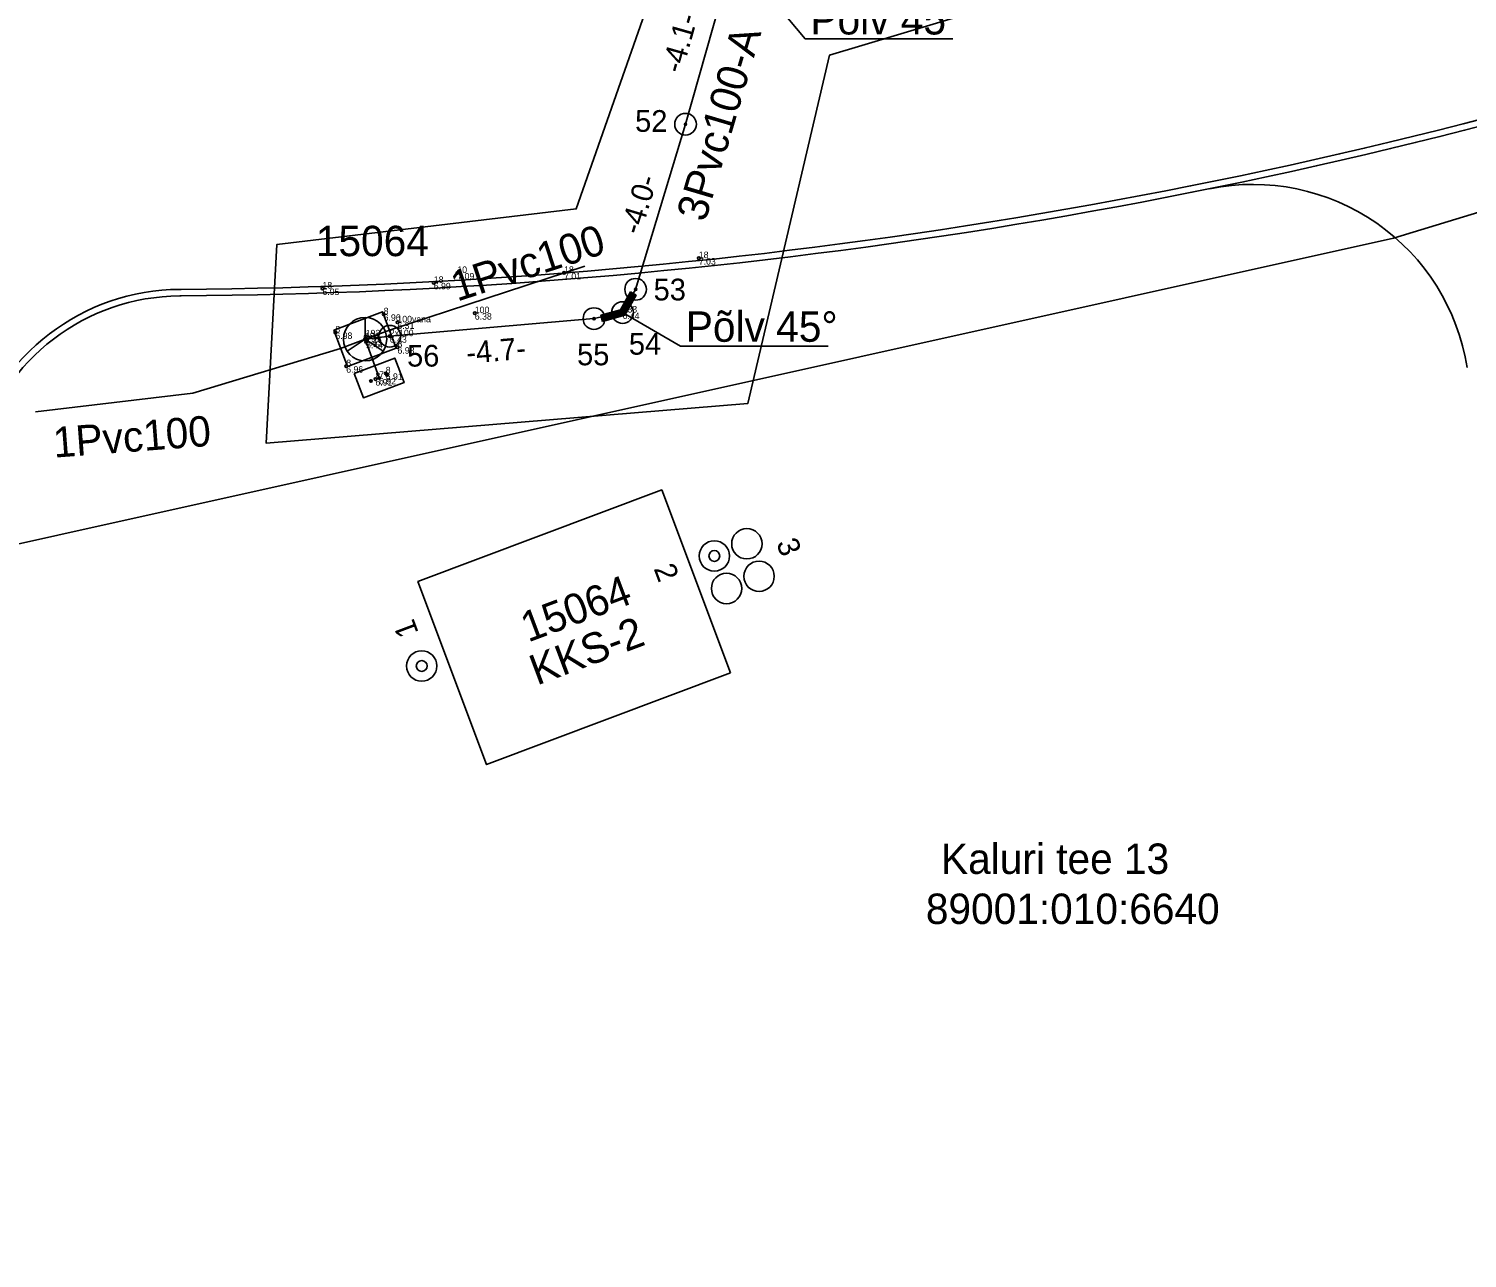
# Model space of a CAD drawing. Extents: x 546339 to 546593, y 6597108 to 6597251.
# Drawn here: x 546356.18 to 546389.31, y 6597127.93 to 6597156.24 of the extents above; entities that cross this region are included whole.
import ezdxf

# ---------------------------------------------------------------- set-up
doc = ezdxf.new("R2010")
doc.units = 0
for name, color, linetype in [('ABIJOONIS', 7, 'Continuous'), ('JOONSIDE', 7, 'Continuous'), ('KAEVUNR_SIKAEV', 7, 'Continuous'), ('KOORDPUNKT', 7, 'Continuous'), ('MOOTKORG-EH2000', 7, 'Continuous'), ('MOOTMPUNKT', 7, 'Continuous'), ('MOOTNR', 7, 'Continuous'), ('MOOTPIIR', 7, 'Continuous'), ('PIIR', 7, 'Continuous'), ('SIKAEV', 7, 'Continuous'), ('SIRAJATIS', 7, 'Continuous'), ('SITRASS', 7, 'Continuous'), ('TEE', 7, 'Continuous')]:
    doc.layers.add(name, color=color, linetype=linetype)

msp = doc.modelspace()

# ---------------------------------------------------------------- linework, layer by layer
at = {"layer": 'ABIJOONIS'}
msp.add_lwpolyline([(546372.341, 6597141.406), (546366.724, 6597139.295), (546365.141, 6597143.507), (546370.757, 6597145.618)], close=True, dxfattribs=at)
for centre, radius in [((546372.719, 6597144.379), 0.35), ((546371.97, 6597144.098), 0.35), ((546371.97, 6597144.098), 0.124), ((546373, 6597143.63), 0.35), ((546372.251, 6597143.349), 0.35), ((546365.23, 6597141.564), 0.35), ((546365.23, 6597141.564), 0.124)]:
    msp.add_circle(centre, radius, dxfattribs=at)
at = {"layer": 'KOORDPUNKT'}
for centre, radius in [((546371.306, 6597154.04), 0.25), ((546371.306, 6597154.04), 0.025), ((546371.306, 6597154.04), 0.0221), ((546371.306, 6597154.04), 0.0191), ((546371.306, 6597154.04), 0.0161), ((546371.306, 6597154.04), 0.0132), ((546371.306, 6597154.04), 0.0102), ((546371.306, 6597154.04), 0.00726), ((546371.306, 6597154.04), 0.0043), ((546370.157, 6597150.238), 0.25), ((546370.157, 6597150.238), 0.025), ((546370.157, 6597150.238), 0.0221), ((546370.157, 6597150.238), 0.0191), ((546370.157, 6597150.238), 0.0161), ((546370.157, 6597150.238), 0.0132), ((546369.857, 6597149.704), 0.25), ((546370.157, 6597150.238), 0.0102), ((546370.157, 6597150.238), 0.00726), ((546370.157, 6597150.238), 0.0043), ((546369.198, 6597149.563), 0.25), ((546369.857, 6597149.704), 0.025), ((546369.857, 6597149.704), 0.0221), ((546369.857, 6597149.704), 0.0191), ((546369.857, 6597149.704), 0.0161), ((546369.857, 6597149.704), 0.0132), ((546369.857, 6597149.704), 0.0102), ((546369.857, 6597149.704), 0.00726), ((546369.857, 6597149.704), 0.0043), ((546364.495, 6597149.159), 0.25), ((546369.198, 6597149.563), 0.025), ((546369.198, 6597149.563), 0.0221), ((546369.198, 6597149.563), 0.0191), ((546369.198, 6597149.563), 0.0161), ((546369.198, 6597149.563), 0.0132), ((546369.198, 6597149.563), 0.0102), ((546369.198, 6597149.563), 0.00726), ((546369.198, 6597149.563), 0.0043), ((546364.495, 6597149.159), 0.025), ((546364.495, 6597149.159), 0.0221), ((546364.495, 6597149.159), 0.0191), ((546364.495, 6597149.159), 0.0161), ((546364.495, 6597149.159), 0.0132), ((546364.495, 6597149.159), 0.0102), ((546364.495, 6597149.159), 0.00726), ((546364.495, 6597149.159), 0.0043)]:
    msp.add_circle(centre, radius, dxfattribs=at)
at = {"layer": 'MOOTMPUNKT'}
for centre in [(546371.612, 6597150.957), (546366.051, 6597150.615), (546368.509, 6597150.618), (546362.944, 6597150.256), (546365.508, 6597150.387), (546364.354, 6597149.663), (546366.453, 6597149.69), (546369.857, 6597149.704), (546363.242, 6597149.245), (546364.671, 6597149.478), (546363.925, 6597149.09), (546363.941, 6597149.155), (546363.948, 6597149.028), (546364.495, 6597149.159), (546364.672, 6597148.906), (546363.492, 6597148.469), (546364.401, 6597148.303), (546364.164, 6597148.172), (546364.248, 6597148.197)]:
    msp.add_circle(centre, 0.03, dxfattribs=at)
at = {"layer": 'MOOTPIIR'}
msp.add_lwpolyline([(546443.888, 6597176.348), (546374.62, 6597155.63), (546372.739, 6597147.606), (546361.644, 6597146.697), (546361.895, 6597151.274), (546368.79, 6597152.088), (546371.486, 6597159.799), (546428.467, 6597177.226), (546428.906, 6597181.927), (546431.038, 6597182.742), (546435.363, 6597179.169)], dxfattribs=at)
at = {"layer": 'PIIR'}
for points in [[(546339.379, 6597150.424), (546339.82, 6597150.4), (546343.3, 6597148.09), (546350.66, 6597143.2), (546387.61, 6597151.42), (546402.5, 6597155.95), (546434.27, 6597166.43), (546452.55, 6597172.32), (546467.66, 6597177.18), (546479.16, 6597180.72), (546505.65, 6597188.82)], [(546405.647, 6597133.544), (546402.5, 6597155.95), (546387.61, 6597151.42), (546350.66, 6597143.2), (546352.148, 6597127.926)]]:
    msp.add_lwpolyline(points, dxfattribs=at)
at = {"layer": 'SIKAEV'}
for p, q in [((546363.925, 6597149.59), (546363.925, 6597149.09)), ((546363.925, 6597149.09), (546363.51, 6597148.815)), ((546363.925, 6597149.09), (546364.34, 6597148.815))]:
    msp.add_line(p, q, dxfattribs=at)
msp.add_lwpolyline([(546363.205, 6597149.3), (546364.328, 6597149.722), (546364.645, 6597148.88), (546363.522, 6597148.458)], close=True, dxfattribs=at)
msp.add_circle((546363.925, 6597149.09), 0.5, dxfattribs=at)
at = {"layer": 'SIRAJATIS'}
msp.add_lwpolyline([(546363.674, 6597148.302), (546364.61, 6597148.654), (546364.822, 6597148.092), (546363.886, 6597147.74)], close=True, dxfattribs=at)
for centre, radius in [((546364.435, 6597148.267), 0.0304), ((546364.435, 6597148.267), 0.029), ((546364.435, 6597148.267), 0.0277), ((546364.435, 6597148.267), 0.0263), ((546364.435, 6597148.267), 0.0249), ((546364.435, 6597148.267), 0.0236), ((546364.435, 6597148.267), 0.0222), ((546364.435, 6597148.267), 0.0209), ((546364.435, 6597148.267), 0.0195), ((546364.435, 6597148.267), 0.0181), ((546364.435, 6597148.267), 0.0168), ((546364.435, 6597148.267), 0.0154), ((546364.435, 6597148.267), 0.014), ((546364.435, 6597148.267), 0.0127), ((546364.435, 6597148.267), 0.0113), ((546364.435, 6597148.267), 0.00996), ((546364.435, 6597148.267), 0.0086), ((546364.435, 6597148.267), 0.00724), ((546364.435, 6597148.267), 0.00587), ((546364.435, 6597148.267), 0.00451), ((546364.435, 6597148.267), 0.00315), ((546364.435, 6597148.267), 0.00179), ((546364.435, 6597148.267), 0.000426), ((546364.061, 6597148.127), 0.0304), ((546364.061, 6597148.127), 0.029), ((546364.061, 6597148.127), 0.0277), ((546364.061, 6597148.127), 0.0263), ((546364.061, 6597148.127), 0.0249), ((546364.061, 6597148.127), 0.0236), ((546364.061, 6597148.127), 0.0222), ((546364.061, 6597148.127), 0.0209), ((546364.061, 6597148.127), 0.0195), ((546364.061, 6597148.127), 0.0181), ((546364.061, 6597148.127), 0.0168), ((546364.061, 6597148.127), 0.0154), ((546364.061, 6597148.127), 0.014), ((546364.061, 6597148.127), 0.0127), ((546364.061, 6597148.127), 0.0113), ((546364.061, 6597148.127), 0.00996), ((546364.061, 6597148.127), 0.0086), ((546364.061, 6597148.127), 0.00724), ((546364.061, 6597148.127), 0.00587), ((546364.061, 6597148.127), 0.00451), ((546364.061, 6597148.127), 0.00315), ((546364.061, 6597148.127), 0.00179), ((546364.061, 6597148.127), 0.000426)]:
    msp.add_circle(centre, radius, dxfattribs=at)
at = {"layer": 'SITRASS'}
for p, q in [((546370.037, 6597150.177), (546369.807, 6597149.768)), ((546370.102, 6597150.14), (546369.857, 6597149.704)), ((546370.167, 6597150.103), (546369.908, 6597149.64)), ((546369.909, 6597149.949), (546369.957, 6597149.728)), ((546369.927, 6597149.981), (546369.975, 6597149.761)), ((546369.945, 6597150.014), (546369.994, 6597149.793)), ((546369.964, 6597150.047), (546370.012, 6597149.826)), ((546369.982, 6597150.08), (546370.03, 6597149.859)), ((546370.001, 6597150.113), (546370.049, 6597149.892)), ((546370.019, 6597150.146), (546370.067, 6597149.925)), ((546370.037, 6597150.177), (546370.167, 6597150.103)), ((546370.038, 6597150.176), (546370.086, 6597149.958)), ((546370.067, 6597150.16), (546370.104, 6597149.991)), ((546370.096, 6597150.143), (546370.123, 6597150.023)), ((546370.126, 6597150.127), (546370.141, 6597150.056)), ((546370.155, 6597150.11), (546370.159, 6597150.089)), ((546369.356, 6597149.641), (546369.807, 6597149.768)), ((546369.356, 6597149.641), (546369.396, 6597149.496)), ((546369.361, 6597149.642), (546369.382, 6597149.548)), ((546369.376, 6597149.569), (546369.857, 6597149.704)), ((546369.385, 6597149.649), (546369.417, 6597149.502)), ((546369.396, 6597149.496), (546369.908, 6597149.64)), ((546369.409, 6597149.656), (546369.442, 6597149.509)), ((546369.434, 6597149.663), (546369.466, 6597149.516)), ((546369.458, 6597149.67), (546369.49, 6597149.523)), ((546369.482, 6597149.676), (546369.514, 6597149.529)), ((546369.506, 6597149.683), (546369.538, 6597149.536)), ((546369.53, 6597149.69), (546369.562, 6597149.543)), ((546369.554, 6597149.697), (546369.586, 6597149.55)), ((546369.578, 6597149.703), (546369.61, 6597149.557)), ((546369.602, 6597149.71), (546369.634, 6597149.563)), ((546369.626, 6597149.717), (546369.658, 6597149.57)), ((546369.651, 6597149.724), (546369.683, 6597149.577)), ((546369.675, 6597149.731), (546369.707, 6597149.584)), ((546369.699, 6597149.737), (546369.731, 6597149.59)), ((546369.723, 6597149.744), (546369.755, 6597149.597)), ((546369.747, 6597149.751), (546369.779, 6597149.604)), ((546369.771, 6597149.758), (546369.803, 6597149.611)), ((546369.795, 6597149.764), (546369.827, 6597149.618)), ((546369.816, 6597149.784), (546369.851, 6597149.624)), ((546369.835, 6597149.817), (546369.875, 6597149.631)), ((546369.853, 6597149.85), (546369.9, 6597149.638)), ((546369.872, 6597149.883), (546369.92, 6597149.662)), ((546369.89, 6597149.916), (546369.938, 6597149.695))]:
    msp.add_line(p, q, dxfattribs=at)
for points in [[(546412.984, 6597169.682), (546404.421, 6597166.986), (546400.555, 6597165.683), (546393.387, 6597163.477), (546387.753, 6597161.903), (546381.148, 6597160.525), (546374.997, 6597158.932), (546372.419, 6597157.971), (546371.306, 6597154.04), (546370.157, 6597150.238), (546369.857, 6597149.704), (546369.198, 6597149.563), (546364.495, 6597149.159), (546363.925, 6597149.09)], [(546377.463, 6597156.009), (546374.06, 6597156.009), (546372.419, 6597157.971)], [(546363.925, 6597149.09), (546364.487, 6597149.301), (546368.99, 6597150.772)], [(546374.593, 6597148.932), (546371.191, 6597148.932), (546369.857, 6597149.704)], [(546363.925, 6597149.09), (546363.363, 6597148.879), (546359.96, 6597147.85), (546356.337, 6597147.414)], [(546364.248, 6597148.197), (546364.083, 6597148.669), (546363.925, 6597149.09)]]:
    msp.add_lwpolyline(points, dxfattribs=at)
at = {"layer": 'TEE'}
for p, q in [((546359.655, 6597150.237), (546359.686, 6597150.237)), ((546359.687, 6597150.087), (546359.687, 6597150.087))]:
    msp.add_line(p, q, dxfattribs=at)
msp.add_lwpolyline([(546359.687, 6597150.087), (546359.656, 6597150.087), (546359.656, 6597150.087)], dxfattribs=at)
for centre, radius, start, end in [((546358.831, 6597273.234), 123, 270.39825, 287.8487), ((546358.831, 6597273.234), 123.15, 270.39825, 287.8487), ((546384.371, 6597147.655), 5, 8.9925, 101.4165), ((546359.689, 6597145.237), 5, 90.3838, 164.3278), ((546359.689, 6597145.237), 4.85, 90.3837, 164.3277)]:
    msp.add_arc(centre, radius, start, end, dxfattribs=at)

# ---------------------------------------------------------------- texts
at = {"layer": 'ABIJOONIS'}
for s, height, rotation, p in [('3', 0.5, 290.6012, (546373.39, 6597144.397)), ('15064', 0.7, 20.6012, (546367.68, 6597142.102)), ('2', 0.5, 290.6012, (546370.568, 6597143.809)), ('1', 0.5, 110.6012, (546365.165, 6597142.33)), ('KKS-2', 0.7, 20.6012, (546367.884, 6597141.111))]:
    msp.add_text(s, height=height, rotation=rotation, dxfattribs=at).set_placement(p)
at = {"layer": 'JOONSIDE'}
for s, rotation, p in [('-4.1-', 74.1952, (546371.221, 6597155.188)), ('-4.0-', 73.1781, (546370.268, 6597151.47)), ('-4.7-', 4.9098, (546366.276, 6597148.525))]:
    msp.add_text(s, height=0.5, rotation=rotation, dxfattribs=at).set_placement(p)
at = {"layer": 'KAEVUNR_SIKAEV'}
msp.add_text('15064', height=0.7, dxfattribs=at).set_placement((546362.792, 6597151.002))
at = {"layer": 'KOORDPUNKT'}
for s, p in [('52', (546370.145, 6597153.865)), ('53', (546370.571, 6597149.983)), ('56', (546364.893, 6597148.459)), ('55', (546368.808, 6597148.489)), ('54', (546370.001, 6597148.733))]:
    msp.add_text(s, height=0.5, dxfattribs=at).set_placement(p)
at = {"layer": 'MOOTKORG-EH2000'}
for s, p in [('7.03', (546371.612, 6597150.807)), ('7.09', (546366.051, 6597150.465)), ('7.01', (546368.509, 6597150.468)), ('6.95', (546362.944, 6597150.106)), ('6.99', (546365.508, 6597150.237)), ('6.96', (546364.354, 6597149.513)), ('6.38', (546366.453, 6597149.54)), ('6.44', (546369.857, 6597149.554)), ('6.31', (546364.671, 6597149.328)), ('6.98', (546363.242, 6597149.095)), ('5.43', (546363.925, 6597148.94)), ('7.11', (546363.941, 6597149.005)), ('5.44', (546363.948, 6597148.878)), ('6.43', (546364.495, 6597149.009)), ('6.98', (546364.672, 6597148.756)), ('6.96', (546363.492, 6597148.319)), ('6.91', (546364.401, 6597148.153)), ('6.91', (546364.164, 6597148.022)), ('6.92', (546364.248, 6597148.047))]:
    msp.add_text(s, height=0.15, dxfattribs=at).set_placement(p)
at = {"layer": 'MOOTNR'}
for s, p in [('18', (546371.612, 6597150.957)), ('10', (546366.051, 6597150.615)), ('18', (546368.509, 6597150.618)), ('18', (546362.944, 6597150.256)), ('18', (546365.508, 6597150.387)), ('8', (546364.354, 6597149.663)), ('100vana', (546364.671, 6597149.478)), ('100', (546366.453, 6597149.69)), ('333', (546369.857, 6597149.704)), ('8', (546363.242, 6597149.245)), ('193', (546363.941, 6597149.155)), ('2x100', (546364.495, 6597149.159)), ('191', (546363.925, 6597149.09)), ('191', (546363.948, 6597149.028)), ('8', (546364.672, 6597148.906)), ('8', (546363.492, 6597148.469)), ('8', (546364.164, 6597148.172)), ('7', (546364.248, 6597148.197)), ('8', (546364.401, 6597148.303))]:
    msp.add_text(s, height=0.15, dxfattribs=at).set_placement(p)
at = {"layer": 'PIIR'}
for s, p in [('Kaluri tee 13', (546377.19, 6597136.776)), ('89001:010:6640', (546376.841, 6597135.623))]:
    msp.add_text(s, height=0.7, dxfattribs=at).set_placement(p)
at = {"layer": 'SITRASS'}
for p in [(546374.183, 6597156.107), (546371.313, 6597149.03)]:
    msp.add_text('Põlv 45°', height=0.7, dxfattribs=at).set_placement(p)
for s, rotation, p in [('3Pvc100-A', 73.5304, (546371.759, 6597151.767)), ('1Pvc100', 18.0844, (546366.046, 6597149.952)), ('1Pvc100', 4.3418, (546356.765, 6597146.361))]:
    msp.add_text(s, height=0.7, rotation=rotation, dxfattribs=at).set_placement(p)

doc.saveas('drawing.dxf')
